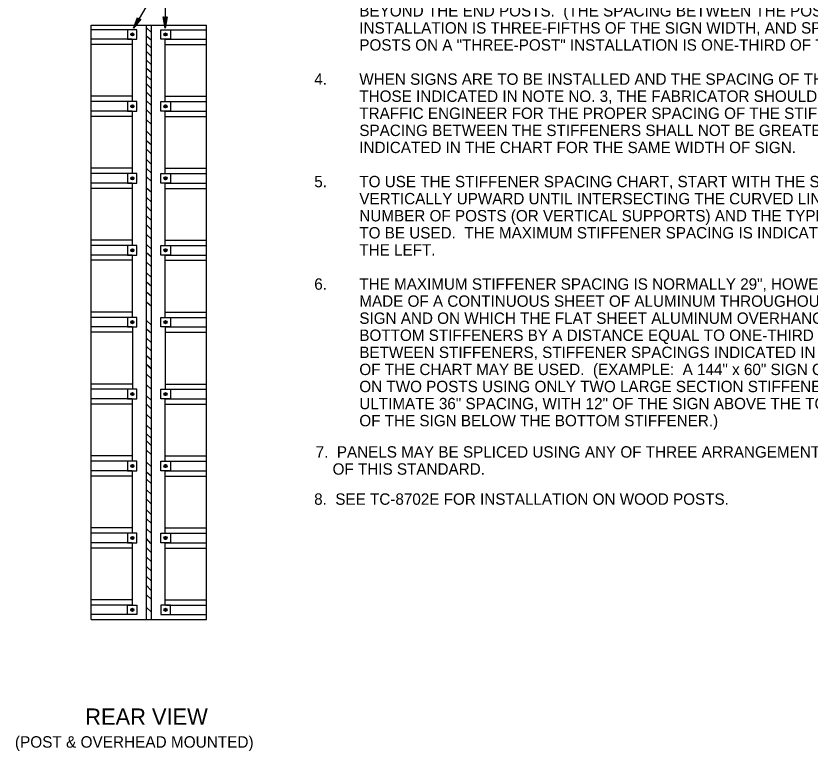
# Model space of a CAD drawing. Extents: x 650495 to 652241, y 298458 to 299646.
# Drawn here: x 650987.1 to 651196.3, y 299351.4 to 299545.2 of the extents above; entities that cross this region are included whole.
import ezdxf

# ---------------------------------------------------------------- set-up
doc = ezdxf.new("R2010")
doc.units = 0
doc.layers.add('2', color=7, linetype='Continuous')
doc.layers.add('3', color=7, linetype='Continuous')

# ---------------------------------------------------------------- blocks, each defined once
blk = doc.blocks.new('RARROW')
at = {"layer": '3'}
blk.add_lwpolyline([(-2.2695, 0.285), (-2.184875, 0.12075), (0, 0), (-2.2695, 0.285), (-2.38575, 0.384625), (0, 0), (-2.183125, -0.108), (-2.262875, -0.2705), (0, 0), (-2.38575, -0.379125), (-2.262875, -0.2705)], dxfattribs=at)

msp = doc.modelspace()

# ---------------------------------------------------------------- linework, layer by layer
at = {"layer": '2'}
for p, q in [((651026.41, 299556.11), (651018.09, 299541.93)), ((651026.41, 299556.11), (651026.4, 299541.95)), ((651006.95, 299386.13), (651006.95, 299542.76)), ((651006.95, 299542.76), (651037.34, 299542.76)), ((651017.72, 299541.53), (651006.95, 299541.53)), ((651019, 299541.53), (651016.48, 299541.53)), ((651016.48, 299541.53), (651016.48, 299539.01)), ((651019, 299539.01), (651019, 299541.53)), ((651021.52, 299386.13), (651021.52, 299542.76)), ((651022.78, 299540.79), (651021.52, 299542.05)), ((651022.78, 299386.13), (651022.78, 299542.76)), ((651025.29, 299539.01), (651025.29, 299541.53)), ((651025.29, 299541.53), (651027.81, 299541.53)), ((651026.58, 299541.53), (651037.34, 299541.53)), ((651027.81, 299541.53), (651027.81, 299539.01)), ((651037.34, 299386.13), (651037.34, 299542.76)), ((651017.72, 299539.01), (651006.95, 299539.01)), ((651016.48, 299539.01), (651019, 299539.01)), ((651017.84, 299522.57), (651017.84, 299539.01)), ((651022.78, 299538.66), (651021.52, 299539.83)), ((651027.81, 299539.01), (651025.29, 299539.01)), ((651026.45, 299522.57), (651026.45, 299539.01)), ((651026.58, 299539.01), (651037.34, 299539.01)), ((651017.84, 299537.61), (651006.95, 299537.61)), ((651022.78, 299536.63), (651021.52, 299537.89)), ((651026.45, 299537.61), (651037.34, 299537.61)), ((651022.78, 299534.5), (651021.52, 299535.76)), ((651022.78, 299532.28), (651021.52, 299533.53)), ((651022.78, 299532.28), (651021.52, 299533.53)), ((651022.78, 299530.15), (651021.52, 299531.31)), ((651022.78, 299528.11), (651021.52, 299529.37)), ((651022.78, 299525.98), (651021.52, 299527.24)), ((651022.78, 299523.76), (651021.52, 299525.02)), ((651017.84, 299523.97), (651006.95, 299523.97)), ((651017.72, 299522.57), (651006.95, 299522.57)), ((651019, 299522.57), (651016.48, 299522.57)), ((651016.48, 299522.57), (651016.48, 299520.05)), ((651019, 299520.05), (651019, 299522.57)), ((651022.78, 299521.53), (651021.52, 299522.79)), ((651025.29, 299520.05), (651025.29, 299522.57)), ((651025.29, 299522.57), (651027.81, 299522.57)), ((651026.45, 299523.97), (651037.34, 299523.97)), ((651026.58, 299522.57), (651037.34, 299522.57)), ((651027.81, 299522.57), (651027.81, 299520.05)), ((651017.72, 299520.05), (651006.95, 299520.05)), ((651016.48, 299520.05), (651019, 299520.05)), ((651017.84, 299503.61), (651017.84, 299520.05)), ((651022.78, 299519.11), (651021.52, 299520.37)), ((651027.81, 299520.05), (651025.29, 299520.05)), ((651026.45, 299503.61), (651026.45, 299520.05)), ((651026.58, 299520.05), (651037.34, 299520.05)), ((651017.84, 299518.66), (651006.95, 299518.66)), ((651026.45, 299518.66), (651037.34, 299518.66)), ((651022.78, 299516.5), (651021.52, 299517.76)), ((651022.78, 299513.5), (651021.52, 299514.75)), ((651022.78, 299511.08), (651021.52, 299512.24)), ((651022.78, 299508.75), (651021.52, 299510.01)), ((651022.78, 299506.04), (651021.52, 299507.3)), ((651017.84, 299505.01), (651006.95, 299505.01)), ((651017.72, 299503.61), (651006.95, 299503.61)), ((651019, 299503.61), (651016.48, 299503.61)), ((651016.48, 299503.61), (651016.48, 299501.1)), ((651019, 299501.1), (651019, 299503.61)), ((651022.78, 299503.72), (651021.52, 299504.98)), ((651025.29, 299501.1), (651025.29, 299503.61)), ((651025.29, 299503.61), (651027.81, 299503.61)), ((651026.45, 299505.01), (651037.34, 299505.01)), ((651026.58, 299503.61), (651037.34, 299503.61)), ((651027.81, 299503.61), (651027.81, 299501.1)), ((651022.78, 299501.49), (651021.52, 299502.75)), ((651017.72, 299501.1), (651006.95, 299501.1)), ((651017.84, 299499.7), (651006.95, 299499.7)), ((651016.48, 299501.1), (651019, 299501.1)), ((651017.84, 299484.66), (651017.84, 299501.1)), ((651022.78, 299498.59), (651021.52, 299499.75)), ((651027.81, 299501.1), (651025.29, 299501.1)), ((651026.45, 299484.66), (651026.45, 299501.1)), ((651026.45, 299499.7), (651037.34, 299499.7)), ((651026.58, 299501.1), (651037.34, 299501.1)), ((651022.78, 299496.07), (651021.52, 299497.33)), ((651022.78, 299493.65), (651021.52, 299494.91)), ((651022.78, 299491.23), (651021.52, 299492.49)), ((651022.78, 299488.81), (651021.52, 299490.07)), ((651022.78, 299486.3), (651021.52, 299487.55)), ((651017.84, 299486.06), (651006.95, 299486.06)), ((651017.72, 299484.66), (651006.95, 299484.66)), ((651019, 299484.66), (651016.48, 299484.66)), ((651016.48, 299484.66), (651016.48, 299482.14)), ((651019, 299482.14), (651019, 299484.66)), ((651022.78, 299483.68), (651021.52, 299484.94)), ((651025.29, 299482.14), (651025.29, 299484.66)), ((651025.29, 299484.66), (651027.81, 299484.66)), ((651026.45, 299486.06), (651037.34, 299486.06)), ((651026.58, 299484.66), (651037.34, 299484.66)), ((651027.81, 299484.66), (651027.81, 299482.14)), ((651022.78, 299481.55), (651021.52, 299482.71)), ((651017.72, 299482.14), (651006.95, 299482.14)), ((651017.84, 299480.75), (651006.95, 299480.75)), ((651016.48, 299482.14), (651019, 299482.14)), ((651017.84, 299465.7), (651017.84, 299482.14)), ((651022.78, 299479.04), (651021.52, 299480.29)), ((651027.81, 299482.14), (651025.29, 299482.14)), ((651026.45, 299465.7), (651026.45, 299482.14)), ((651026.45, 299480.75), (651037.34, 299480.75)), ((651026.58, 299482.14), (651037.34, 299482.14)), ((651022.78, 299476.23), (651021.52, 299477.49)), ((651022.78, 299473.81), (651021.52, 299474.97)), ((651022.78, 299471.19), (651021.52, 299472.36)), ((651022.78, 299468.58), (651021.52, 299469.74)), ((651017.84, 299467.1), (651006.95, 299467.1)), ((651017.72, 299465.7), (651006.95, 299465.7)), ((651019, 299465.7), (651016.48, 299465.7)), ((651016.48, 299465.7), (651016.48, 299463.19)), ((651019, 299463.19), (651019, 299465.7)), ((651025.29, 299463.19), (651025.29, 299465.7)), ((651025.29, 299465.7), (651027.81, 299465.7)), ((651026.45, 299467.1), (651037.34, 299467.1)), ((651026.58, 299465.7), (651037.34, 299465.7)), ((651027.81, 299465.7), (651027.81, 299463.19)), ((651022.78, 299463.64), (651021.52, 299464.9)), ((651017.72, 299463.19), (651006.95, 299463.19)), ((651017.84, 299461.79), (651006.95, 299461.79)), ((651016.48, 299463.19), (651019, 299463.19)), ((651017.84, 299463.19), (651017.84, 299446.75)), ((651022.78, 299461.42), (651021.52, 299462.58)), ((651027.81, 299463.19), (651025.29, 299463.19)), ((651026.45, 299463.19), (651026.45, 299446.75)), ((651026.45, 299461.79), (651037.34, 299461.79)), ((651026.58, 299463.19), (651037.34, 299463.19)), ((651022.78, 299459), (651021.52, 299460.26)), ((651022.78, 299456.77), (651021.52, 299458.03)), ((651022.78, 299454.45), (651021.52, 299455.61)), ((651022.68, 299452.13), (651021.52, 299453.29)), ((651022.78, 299452.13), (651021.52, 299453.29)), ((651022.78, 299449.51), (651021.52, 299450.77)), ((651017.84, 299448.15), (651006.95, 299448.15)), ((651022.78, 299446.7), (651021.52, 299447.96)), ((651026.45, 299448.15), (651037.34, 299448.15)), ((651017.72, 299446.75), (651006.95, 299446.75)), ((651019, 299446.75), (651016.48, 299446.75)), ((651016.48, 299446.75), (651016.48, 299444.23)), ((651019, 299444.23), (651019, 299446.75)), ((651022.78, 299443.8), (651021.52, 299445.06)), ((651025.29, 299444.23), (651025.29, 299446.75)), ((651025.29, 299446.75), (651027.81, 299446.75)), ((651026.58, 299446.75), (651037.34, 299446.75)), ((651027.81, 299446.75), (651027.81, 299444.23)), ((651017.72, 299444.23), (651006.95, 299444.23)), ((651017.84, 299442.83), (651006.95, 299442.83)), ((651016.48, 299444.23), (651019, 299444.23)), ((651017.84, 299427.79), (651017.84, 299444.23)), ((651022.78, 299441.48), (651021.61, 299442.74)), ((651027.81, 299444.23), (651025.29, 299444.23)), ((651026.45, 299427.79), (651026.45, 299444.23)), ((651026.45, 299442.83), (651037.34, 299442.83)), ((651026.58, 299444.23), (651037.34, 299444.23)), ((651022.78, 299438.86), (651021.52, 299440.12)), ((651022.78, 299436.06), (651021.52, 299437.31)), ((651022.78, 299433.83), (651021.52, 299434.99)), ((651022.78, 299431.89), (651021.52, 299433.15)), ((651022.78, 299429.47), (651021.52, 299430.73)), ((651017.84, 299429.19), (651006.95, 299429.19)), ((651026.45, 299429.19), (651037.34, 299429.19)), ((651017.72, 299427.79), (651006.95, 299427.79)), ((651019, 299427.79), (651016.48, 299427.79)), ((651016.48, 299427.79), (651016.48, 299425.28)), ((651019, 299425.28), (651019, 299427.79)), ((651022.78, 299426.28), (651021.52, 299427.54)), ((651025.29, 299425.28), (651025.29, 299427.79)), ((651025.29, 299427.79), (651027.81, 299427.79)), ((651026.58, 299427.79), (651037.34, 299427.79)), ((651027.81, 299427.79), (651027.81, 299425.28)), ((651017.72, 299425.28), (651006.95, 299425.28)), ((651017.84, 299423.88), (651006.95, 299423.88)), ((651016.48, 299425.28), (651019, 299425.28)), ((651017.84, 299408.84), (651017.84, 299425.28)), ((651022.78, 299423.76), (651021.52, 299424.92)), ((651027.81, 299425.28), (651025.29, 299425.28)), ((651026.45, 299408.84), (651026.45, 299425.28)), ((651026.45, 299423.88), (651037.34, 299423.88)), ((651026.58, 299425.28), (651037.34, 299425.28)), ((651022.78, 299421.83), (651021.52, 299423.09)), ((651022.78, 299419.02), (651021.52, 299420.28)), ((651022.78, 299416.5), (651021.52, 299417.76)), ((651022.78, 299413.7), (651021.52, 299414.95)), ((651022.78, 299411.37), (651021.52, 299412.63)), ((651017.84, 299410.24), (651006.95, 299410.24)), ((651022.78, 299408.76), (651021.52, 299410.02)), ((651026.45, 299410.24), (651037.34, 299410.24)), ((651017.72, 299408.84), (651006.95, 299408.84)), ((651019, 299408.84), (651016.48, 299408.84)), ((651016.48, 299408.84), (651016.48, 299406.32)), ((651019, 299406.32), (651019, 299408.84)), ((651022.68, 299406.15), (651021.52, 299407.4)), ((651025.29, 299406.32), (651025.29, 299408.84)), ((651025.29, 299408.84), (651027.81, 299408.84)), ((651026.58, 299408.84), (651037.34, 299408.84)), ((651027.81, 299408.84), (651027.81, 299406.32)), ((651017.72, 299406.32), (651006.95, 299406.32)), ((651016.48, 299406.32), (651019, 299406.32)), ((651017.84, 299389.88), (651017.84, 299406.32)), ((651022.68, 299403.82), (651021.52, 299404.98)), ((651027.81, 299406.32), (651025.29, 299406.32)), ((651026.45, 299389.88), (651026.45, 299406.32)), ((651026.58, 299406.32), (651037.34, 299406.32)), ((651017.84, 299404.92), (651006.95, 299404.92)), ((651026.45, 299404.92), (651037.34, 299404.92)), ((651022.78, 299401.31), (651021.52, 299402.56)), ((651022.78, 299398.79), (651021.61, 299399.95)), ((651022.78, 299396.17), (651021.52, 299397.43)), ((651022.68, 299393.85), (651021.52, 299395.01)), ((651022.78, 299391.33), (651021.52, 299392.59)), ((651017.84, 299391.28), (651006.95, 299391.28)), ((651026.45, 299391.28), (651037.34, 299391.28)), ((651017.72, 299389.88), (651006.95, 299389.88)), ((651016.48, 299389.88), (651019, 299389.88)), ((651016.48, 299387.37), (651016.48, 299389.88)), ((651017.74, 299389.88), (651017.74, 299389.88)), ((651019, 299389.88), (651019, 299387.37)), ((651022.78, 299388.04), (651021.52, 299389.21)), ((651027.81, 299389.88), (651025.29, 299389.88)), ((651025.29, 299389.88), (651025.29, 299387.37)), ((651026.55, 299389.88), (651026.55, 299389.88)), ((651026.58, 299389.88), (651037.34, 299389.88)), ((651027.81, 299387.37), (651027.81, 299389.88)), ((651017.72, 299387.37), (651006.95, 299387.37)), ((651006.95, 299386.13), (651037.34, 299386.13)), ((651019, 299387.37), (651016.48, 299387.37)), ((651025.29, 299387.37), (651027.81, 299387.37)), ((651026.58, 299387.37), (651037.34, 299387.37))]:
    msp.add_line(p, q, dxfattribs=at)
for points in [[(651017.65, 299539.98), (651017.55, 299540.27), (651017.55, 299540.46), (651017.74, 299540.56), (651017.94, 299540.46), (651018.03, 299540.36), (651018.03, 299540.07), (651017.94, 299539.98), (651017.74, 299539.98), (651017.65, 299540.27), (651017.65, 299540.36), (651017.65, 299540.46), (651017.74, 299540.46), (651017.84, 299540.36), (651017.94, 299540.27), (651017.94, 299540.07), (651017.84, 299540.17), (651017.74, 299540.36)], [(651026.65, 299539.98), (651026.75, 299540.27), (651026.75, 299540.46), (651026.55, 299540.56), (651026.36, 299540.46), (651026.26, 299540.36), (651026.26, 299540.07), (651026.36, 299539.98), (651026.55, 299539.98), (651026.65, 299540.27), (651026.65, 299540.36), (651026.65, 299540.46), (651026.55, 299540.46), (651026.45, 299540.36), (651026.36, 299540.27), (651026.36, 299540.07), (651026.45, 299540.17), (651026.55, 299540.36)], [(651017.65, 299521.02), (651017.55, 299521.31), (651017.55, 299521.51), (651017.74, 299521.6), (651017.94, 299521.51), (651018.03, 299521.41), (651018.03, 299521.12), (651017.94, 299521.02), (651017.74, 299521.02), (651017.65, 299521.31), (651017.65, 299521.41), (651017.65, 299521.51), (651017.74, 299521.51), (651017.84, 299521.41), (651017.94, 299521.31), (651017.94, 299521.12), (651017.84, 299521.22), (651017.74, 299521.41)], [(651026.65, 299521.02), (651026.75, 299521.31), (651026.75, 299521.51), (651026.55, 299521.6), (651026.36, 299521.51), (651026.26, 299521.41), (651026.26, 299521.12), (651026.36, 299521.02), (651026.55, 299521.02), (651026.65, 299521.31), (651026.65, 299521.41), (651026.65, 299521.51), (651026.55, 299521.51), (651026.45, 299521.41), (651026.36, 299521.31), (651026.36, 299521.12), (651026.45, 299521.22), (651026.55, 299521.41)], [(651017.65, 299502.07), (651017.55, 299502.36), (651017.55, 299502.55), (651017.74, 299502.65), (651017.94, 299502.55), (651018.03, 299502.45), (651018.03, 299502.16), (651017.94, 299502.07), (651017.74, 299502.07), (651017.65, 299502.36), (651017.65, 299502.45), (651017.65, 299502.55), (651017.74, 299502.55), (651017.84, 299502.45), (651017.94, 299502.36), (651017.94, 299502.16), (651017.84, 299502.26), (651017.74, 299502.45)], [(651026.65, 299502.07), (651026.75, 299502.36), (651026.75, 299502.55), (651026.55, 299502.65), (651026.36, 299502.55), (651026.26, 299502.45), (651026.26, 299502.16), (651026.36, 299502.07), (651026.55, 299502.07), (651026.65, 299502.36), (651026.65, 299502.45), (651026.65, 299502.55), (651026.55, 299502.55), (651026.45, 299502.45), (651026.36, 299502.36), (651026.36, 299502.16), (651026.45, 299502.26), (651026.55, 299502.45)], [(651017.65, 299483.11), (651017.55, 299483.4), (651017.55, 299483.59), (651017.74, 299483.69), (651017.94, 299483.59), (651018.03, 299483.5), (651018.03, 299483.21), (651017.94, 299483.11), (651017.74, 299483.11), (651017.65, 299483.4), (651017.65, 299483.5), (651017.65, 299483.59), (651017.74, 299483.59), (651017.84, 299483.5), (651017.94, 299483.4), (651017.94, 299483.21), (651017.84, 299483.3), (651017.74, 299483.5)], [(651026.65, 299483.11), (651026.75, 299483.4), (651026.75, 299483.59), (651026.55, 299483.69), (651026.36, 299483.59), (651026.26, 299483.5), (651026.26, 299483.21), (651026.36, 299483.11), (651026.55, 299483.11), (651026.65, 299483.4), (651026.65, 299483.5), (651026.65, 299483.59), (651026.55, 299483.59), (651026.45, 299483.5), (651026.36, 299483.4), (651026.36, 299483.21), (651026.45, 299483.3), (651026.55, 299483.5)], [(651017.65, 299464.16), (651017.55, 299464.45), (651017.55, 299464.64), (651017.74, 299464.74), (651017.94, 299464.64), (651018.03, 299464.54), (651018.03, 299464.25), (651017.94, 299464.16), (651017.74, 299464.16), (651017.65, 299464.45), (651017.65, 299464.54), (651017.65, 299464.64), (651017.74, 299464.64), (651017.84, 299464.54), (651017.94, 299464.45), (651017.94, 299464.25), (651017.84, 299464.35), (651017.74, 299464.54)], [(651026.65, 299464.16), (651026.75, 299464.45), (651026.75, 299464.64), (651026.55, 299464.74), (651026.36, 299464.64), (651026.26, 299464.54), (651026.26, 299464.25), (651026.36, 299464.16), (651026.55, 299464.16), (651026.65, 299464.45), (651026.65, 299464.54), (651026.65, 299464.64), (651026.55, 299464.64), (651026.45, 299464.54), (651026.36, 299464.45), (651026.36, 299464.25), (651026.45, 299464.35), (651026.55, 299464.54)], [(651017.65, 299445.2), (651017.55, 299445.49), (651017.55, 299445.68), (651017.74, 299445.78), (651017.94, 299445.68), (651018.03, 299445.59), (651018.03, 299445.3), (651017.94, 299445.2), (651017.74, 299445.2), (651017.65, 299445.49), (651017.65, 299445.59), (651017.65, 299445.68), (651017.74, 299445.68), (651017.84, 299445.59), (651017.94, 299445.49), (651017.94, 299445.3), (651017.84, 299445.39), (651017.74, 299445.59)], [(651026.65, 299445.2), (651026.75, 299445.49), (651026.75, 299445.68), (651026.55, 299445.78), (651026.36, 299445.68), (651026.26, 299445.59), (651026.26, 299445.3), (651026.36, 299445.2), (651026.55, 299445.2), (651026.65, 299445.49), (651026.65, 299445.59), (651026.65, 299445.68), (651026.55, 299445.68), (651026.45, 299445.59), (651026.36, 299445.49), (651026.36, 299445.3), (651026.45, 299445.39), (651026.55, 299445.59)], [(651017.65, 299426.24), (651017.55, 299426.54), (651017.55, 299426.73), (651017.74, 299426.83), (651017.94, 299426.73), (651018.03, 299426.63), (651018.03, 299426.34), (651017.94, 299426.24), (651017.74, 299426.24), (651017.65, 299426.54), (651017.65, 299426.63), (651017.65, 299426.73), (651017.74, 299426.73), (651017.84, 299426.63), (651017.94, 299426.54), (651017.94, 299426.34), (651017.84, 299426.44), (651017.74, 299426.63)], [(651026.65, 299426.24), (651026.75, 299426.54), (651026.75, 299426.73), (651026.55, 299426.83), (651026.36, 299426.73), (651026.26, 299426.63), (651026.26, 299426.34), (651026.36, 299426.24), (651026.55, 299426.24), (651026.65, 299426.54), (651026.65, 299426.63), (651026.65, 299426.73), (651026.55, 299426.73), (651026.45, 299426.63), (651026.36, 299426.54), (651026.36, 299426.34), (651026.45, 299426.44), (651026.55, 299426.63)], [(651017.65, 299407.29), (651017.55, 299407.58), (651017.55, 299407.77), (651017.74, 299407.87), (651017.94, 299407.77), (651018.03, 299407.68), (651018.03, 299407.39), (651017.94, 299407.29), (651017.74, 299407.29), (651017.65, 299407.58), (651017.65, 299407.68), (651017.65, 299407.77), (651017.74, 299407.77), (651017.84, 299407.68), (651017.94, 299407.58), (651017.94, 299407.39), (651017.84, 299407.48), (651017.74, 299407.68)], [(651026.65, 299407.29), (651026.75, 299407.58), (651026.75, 299407.77), (651026.55, 299407.87), (651026.36, 299407.77), (651026.26, 299407.68), (651026.26, 299407.39), (651026.36, 299407.29), (651026.55, 299407.29), (651026.65, 299407.58), (651026.65, 299407.68), (651026.65, 299407.77), (651026.55, 299407.77), (651026.45, 299407.68), (651026.36, 299407.58), (651026.36, 299407.39), (651026.45, 299407.48), (651026.55, 299407.68)], [(651017.65, 299388.91), (651017.55, 299388.62), (651017.55, 299388.43), (651017.74, 299388.33), (651017.94, 299388.43), (651018.03, 299388.53), (651018.03, 299388.82), (651017.94, 299388.91), (651017.74, 299388.91), (651017.65, 299388.62), (651017.65, 299388.53), (651017.65, 299388.43), (651017.74, 299388.43), (651017.84, 299388.53), (651017.94, 299388.62), (651017.94, 299388.82), (651017.84, 299388.72), (651017.74, 299388.53)], [(651026.65, 299388.91), (651026.75, 299388.62), (651026.75, 299388.43), (651026.55, 299388.33), (651026.36, 299388.43), (651026.26, 299388.53), (651026.26, 299388.82), (651026.36, 299388.91), (651026.55, 299388.91), (651026.65, 299388.62), (651026.65, 299388.53), (651026.65, 299388.43), (651026.55, 299388.43), (651026.45, 299388.53), (651026.36, 299388.62), (651026.36, 299388.82), (651026.45, 299388.72), (651026.55, 299388.53)]]:
    msp.add_lwpolyline(points, dxfattribs=at)
for centre in [(651017.78, 299540.27), (651026.51, 299540.27), (651017.78, 299521.31), (651026.51, 299521.31), (651017.78, 299502.36), (651026.51, 299502.36), (651017.78, 299483.4), (651026.51, 299483.4), (651017.78, 299464.45), (651026.51, 299464.45), (651017.78, 299445.49), (651026.51, 299445.49), (651017.78, 299426.53), (651026.51, 299426.53), (651017.78, 299407.58), (651026.51, 299407.58), (651017.78, 299388.63), (651026.51, 299388.63)]:
    msp.add_circle(centre, 0.407, dxfattribs=at)

# ---------------------------------------------------------------- block references
at = {"layer": '2', "yscale": 1.3092961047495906}
for p, xscale, rotation in [((651018.09, 299541.93), 1.257434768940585, -120.29357719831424), ((651026.4, 299541.95), 1.2574347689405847, -90.00000000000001)]:
    msp.add_blockref('RARROW', p, dxfattribs=dict(at, xscale=xscale, rotation=rotation))

# ---------------------------------------------------------------- texts
at = {"layer": '2'}
for s, height, p in [('BEYOND THE END POSTS.  (THE SPACING BETWEEN THE POSTS ON A "TWO-POST" ', 3, (651077.56, 299545)), ('INSTALLATION IS THREE-FIFTHS OF THE SIGN WIDTH, AND SPACING BETWEEN THE ', 3, (651077.56, 299540.5)), ('POSTS ON A "THREE-POST" INSTALLATION IS ONE-THIRD OF THE SIGN WIDTH.)', 3, (651077.56, 299536)), ('4.  ', 3, (651065.69, 299527)), ('WHEN SIGNS ARE TO BE INSTALLED AND THE SPACING OF THE POSTS IS OTHER THAN ', 3, (651077.56, 299527)), ('THOSE INDICATED IN NOTE NO. 3, THE FABRICATOR SHOULD CONSULT THE DISTRICT ', 3, (651077.56, 299522.5)), ('TRAFFIC ENGINEER FOR THE PROPER SPACING OF THE STIFFENERS.  HOWEVER, THE ', 3, (651077.56, 299518)), ('SPACING BETWEEN THE STIFFENERS SHALL NOT BE GREATER THAN THE SPACING ', 3, (651077.56, 299513.5)), ('INDICATED IN THE CHART FOR THE SAME WIDTH OF SIGN.', 3, (651077.56, 299509)), ('5.  ', 2.999, (651065.69, 299500)), ('TO USE THE STIFFENER SPACING CHART, START WITH THE SIGN WIDTH AND GO', 3, (651077.56, 299500)), ('VERTICALLY UPWARD UNTIL INTERSECTING THE CURVED LINE INDICATING THE PROPER', 3, (651077.56, 299495.5)), ('NUMBER OF POSTS (OR VERTICAL SUPPORTS) AND THE TYPE OF STIFFENER SECTION', 3, (651077.56, 299491)), ('TO BE USED.  THE MAXIMUM STIFFENER SPACING IS INDICATED HORIZONTALLY TO', 3, (651077.56, 299486.5)), ('THE LEFT.', 3, (651077.56, 299482)), ('6.  ', 2.999, (651065.69, 299473)), ('THE MAXIMUM STIFFENER SPACING IS NORMALLY 29", HOWEVER, FOR SIGNS', 3, (651077.56, 299473)), ('MADE OF A CONTINUOUS SHEET OF ALUMINUM THROUGHOUT THE HEIGHT OF THE ', 3, (651077.56, 299468.5)), ('SIGN AND ON WHICH THE FLAT SHEET ALUMINUM OVERHANGS BOTH THE TOP AND ', 3, (651077.56, 299464)), ('BOTTOM STIFFENERS BY A DISTANCE EQUAL TO ONE-THIRD OF THE SPACING', 3, (651077.56, 299459.5)), ('BETWEEN STIFFENERS, STIFFENER SPACINGS INDICATED IN THE SHADED PORTION', 3, (651077.56, 299455)), ('OF THE CHART MAY BE USED.  (EXAMPLE:  A 144" x 60" SIGN COULD BE INSTALLED', 3, (651077.56, 299450.5)), ('ON TWO POSTS USING ONLY TWO LARGE SECTION STIFFENERS SPACED AT THE', 3, (651077.56, 299446)), ('ULTIMATE 36" SPACING, WITH 12" OF THE SIGN ABOVE THE TOP STIFFENER AND 12"', 3, (651077.56, 299441.5)), ('OF THE SIGN BELOW THE BOTTOM STIFFENER.)', 3, (651077.56, 299437)), ('7.  PANELS MAY BE SPLICED USING ANY OF THREE ARRANGEMENTS SHOWN ON SHEET 2', 3, (651066.06, 299428.75)), ('    OF THIS STANDARD.', 3, (651066.06, 299424.25)), ('8.  SEE TC-8702E FOR INSTALLATION ON WOOD POSTS.', 3, (651065.66, 299416.32)), ('REAR VIEW', 4.3, (651005.37, 299358.34)), ('(POST & OVERHEAD MOUNTED)', 3.0217, (650986.85, 299352.31))]:
    msp.add_text(s, height=height, dxfattribs=at).set_placement(p)

doc.saveas('drawing.dxf')
